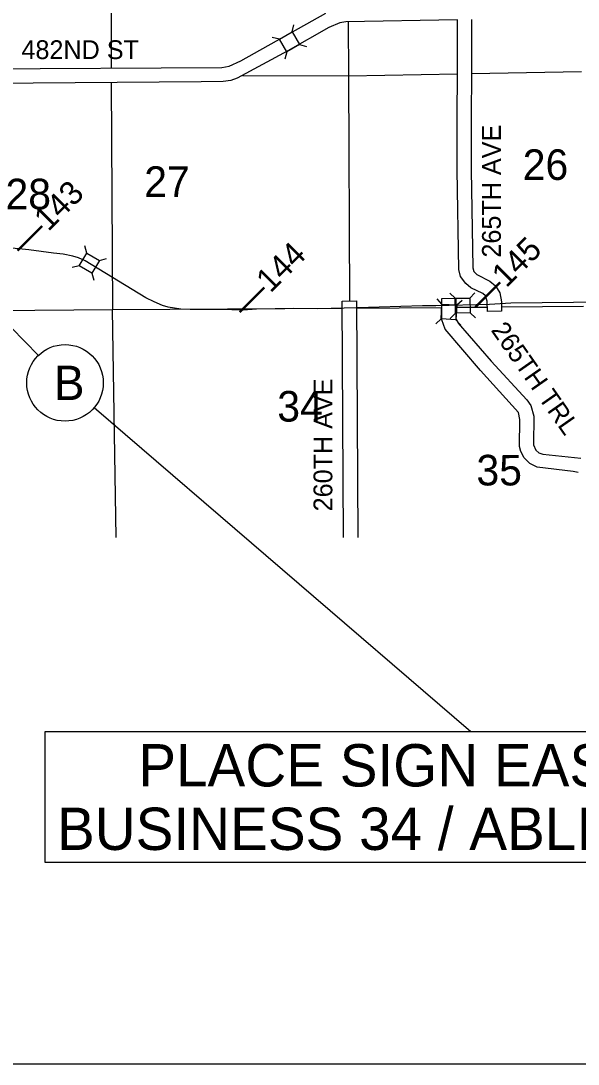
# Model space of a CAD drawing. Extents: x 10133 to 81668, y 5524 to 11018.
# Drawn here: x 18720 to 19016, y 7924 to 8478 of the extents above; entities that cross this region are included whole.
import ezdxf

# ---------------------------------------------------------------- set-up
doc = ezdxf.new("R2010")
doc.units = 0
for name, color, linetype in [('Default', 7, 'Continuous'), ('DisCLMLSUR', 7, 'Continuous'), ('DsnShtRevisedText', 7, 'Continuous'), ('Level 3', 7, 'Continuous'), ('trf_Signal_(Temp)_Layout', 7, 'Continuous'), ('trf_SignNumber_Text', 7, 'Continuous')]:
    doc.layers.add(name, color=color, linetype=linetype)

msp = doc.modelspace()

# ---------------------------------------------------------------- linework, layer by layer
at = {"layer": 'Default'}
for p, q in [((18864.39, 8472.6), (18865.4, 8476.38)), ((18857.62, 8468.67), (18853.84, 8469.67)), ((18861.55, 8461.9), (18860.55, 8458.12)), ((18868.32, 8465.83), (18872.1, 8464.83)), ((18755.3, 8355.06), (18754.32, 8358.85)), ((18762.05, 8351.09), (18765.83, 8352.07)), ((18751.33, 8348.31), (18747.55, 8347.33)), ((18758.08, 8344.35), (18759.06, 8340.56)), ((18950.99, 8330.98), (18948.17, 8333.69)), ((18958.82, 8331.13), (18961.53, 8333.95)), ((18944.03, 8327.85), (18941.41, 8330.76)), ((18951.84, 8327.44), (18954.75, 8330.06)), ((18951.15, 8323.15), (18948.44, 8320.33)), ((18958.97, 8323.31), (18961.79, 8320.6)), ((18943.61, 8320.04), (18940.71, 8317.42)), ((18951.43, 8319.63), (18954.05, 8316.72))]:
    msp.add_line(p, q, dxfattribs=at)
for points in [[(18768.34, 8571.32), (18768.32, 8453.2)], [(18646.39, 8479.35), (18687.6, 8455.98), (18692.87, 8453.87), (18698.1, 8452.88), (18827.11, 8453.63), (18830.92, 8454.32), (18837.18, 8457.2), (18882.24, 8482.55)], [(18959.72, 8479.16), (18959.57, 8399.1), (18960.38, 8347.18), (18961.03, 8345.29), (18962.49, 8343.61), (18969.52, 8340.11), (18972.53, 8337.59), (18974.68, 8333.93), (18975.61, 8329.14), (18975.73, 8324.24), (18968.24, 8324.05), (18968.03, 8329.55), (18967.1, 8332.37), (18965.77, 8333.62), (18959.43, 8336.6), (18956.64, 8338.81), (18953.95, 8342.63), (18952.93, 8346.28), (18952.07, 8399.04), (18952.23, 8478.98), (18893.02, 8477.95), (18889.77, 8477.47), (18883.84, 8474.97), (18862.21, 8462.48), (18835.2, 8447.91), (18831.85, 8446.77), (18827.8, 8446.16), (18816.05, 8445.98), (18704.28, 8445.21)], [(18894.17, 8477.97), (18894.28, 8449.2)], [(18838.07, 8449.31), (18894.28, 8449.2)], [(18894.28, 8449.2), (18952.28, 8450.32)], [(18959.78, 8450.47), (19018.07, 8451.6)], [(18768.34, 8445.73), (18769.03, 8325.06)], [(18894.28, 8449.2), (18894.82, 8329.55)], [(18891.76, 8203.88), (18891.03, 8329.49), (18898.53, 8329.61), (18899.25, 8203.88)], [(19016.38, 8238.34), (19013.68, 8239.04), (18994.63, 8241.18), (18990.69, 8243.2), (18987.67, 8246.19), (18985.93, 8249.54), (18985.2, 8252.25), (18985.32, 8266.6), (18984.66, 8270.31), (18964.56, 8292.63), (18945.67, 8314.52), (18943.96, 8319.56), (18943.9, 8330.83), (18951.4, 8331.02), (18951.4, 8320.47), (18952.54, 8317.77), (18970.18, 8297.59), (18989.09, 8276.96), (18991.17, 8274.08), (18992.76, 8268.28), (18992.68, 8253.05), (18993.96, 8250.35), (18995.55, 8248.95), (18997.55, 8248.16), (19017.72, 8246.02)], [(18645.13, 8323.93), (18769.03, 8325.06)], [(18769.03, 8325.06), (18891.06, 8325.77)], [(18770.9, 8203.88), (18769.03, 8325.06)], [(18898.55, 8325.82), (18944.03, 8326.18)], [(18951.53, 8326.24), (18968.15, 8326.37)], [(18975.68, 8326.43), (19019.13, 8326.78)]]:
    msp.add_lwpolyline(points, dxfattribs=at)
for points in [[(18857.62, 8468.67), (18864.39, 8472.6), (18868.32, 8465.83), (18861.55, 8461.9)], [(18755.3, 8355.06), (18762.05, 8351.09), (18758.08, 8344.35), (18751.33, 8348.31)], [(18943.61, 8320.04), (18944.03, 8327.85), (18951.84, 8327.44), (18951.43, 8319.63)], [(18950.99, 8330.98), (18958.82, 8331.13), (18958.97, 8323.31), (18951.15, 8323.15)]]:
    msp.add_lwpolyline(points, close=True, dxfattribs=at)
at = {"layer": 'DisCLMLSUR'}
msp.add_line((18688.77, 8342.47), (18729.58, 8300.61), dxfattribs=at)
at = {"layer": 'DsnShtRevisedText'}
msp.add_lwpolyline([(19037.37, 8329.05), (19013.82, 8328.77), (18980.53, 8328.4), (18969.34, 8327.78), (18940.67, 8326.92), (18933.67, 8327.01), (18899.07, 8325.9), (18878.02, 8325.4), (18865.16, 8325.5), (18845.43, 8325.28), (18838.4, 8324.76), (18826.1, 8325), (18810.23, 8325.06), (18805.2, 8325.19), (18798.54, 8326.28), (18795.6, 8327.15), (18791.04, 8329.03), (18786.65, 8331.29), (18754.41, 8350.97), (18750.9, 8352.51), (18747.99, 8353.38), (18742.81, 8354.44), (18737.57, 8355.06), (18724.56, 8356.69), (18693.53, 8359.83)], dxfattribs=at)
at = {"layer": 'Level 3'}
msp.add_lwpolyline([(17332.52, 9944.02), (20467.53, 9944.02), (20467.53, 7924.02), (17332.52, 7924.02)], close=True, dxfattribs=at)
at = {"layer": 'trf_Signal_(Temp)_Layout'}
msp.add_line((18959.38, 8100.58), (18759.18, 8272.8), dxfattribs=at)
msp.add_lwpolyline([(18732.97, 8031.33), (19185.79, 8031.33), (19185.79, 8100.58), (18732.97, 8100.58)], close=True, dxfattribs=at)
at = {"layer": 'trf_SignNumber_Text'}
msp.add_circle((18743.77, 8286.06), 20.33, dxfattribs=at)

# ---------------------------------------------------------------- texts
at = {"layer": 'Default'}
msp.add_text('482ND ST', height=10, dxfattribs=at).set_placement((18720.6, 8458.12))
for s, height, rotation, p in [('265TH AVE', 10, 90, (18975.3, 8352.62)), ('26', 16.25, 0.0113, (18986.93, 8393.9)), ('27', 16.25, 0.0094, (18785.86, 8384.88)), ('28', 16.25, 0.0094, (18712.14, 8378.29)), ('‒‒143', 12.5, 45, (18721.77, 8353.01)), ('‒‒144', 12.5, 45, (18839.76, 8320.34)), ('‒‒145', 12.5, 45, (18964.99, 8323.06)), ('265TH TRL', 10, 305, (18969.73, 8314.04)), ('260TH AVE', 10, 90, (18885.77, 8217.77)), ('34', 16.25, 0.0094, (18856.52, 8265.49)), ('35', 16.25, 0.0113, (18962.33, 8231.55))]:
    msp.add_text(s, height=height, rotation=rotation, dxfattribs=at).set_placement(p)
at = {"layer": 'DisCLMLSUR'}
for s, p in [('PLACE SIGN EAST OF ', (18782.66, 8071.58)), ('BUSINESS 34 / ABLIA ROAD', (18739.47, 8037.83))]:
    msp.add_text(s, height=22.5, dxfattribs=at).set_placement(p)
at = {"layer": 'trf_SignNumber_Text'}
msp.add_text('B', height=18.26, dxfattribs=at).set_placement((18737.8, 8276.93))

doc.saveas('drawing.dxf')
